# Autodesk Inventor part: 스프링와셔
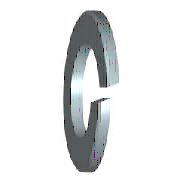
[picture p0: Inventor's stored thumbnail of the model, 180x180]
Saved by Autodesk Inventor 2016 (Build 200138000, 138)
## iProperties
Created: 2012-02
Part Number: 스프링와셔
Material: 강철, 연강
Description: 스프링 와셔
Document SubType Name: Modeling
Standard: JIS B 1251
Designer: mduedu
Standards Organization: JIS
Language: ko-KR
Size Designation: 번호 2 4
Categories: <MemberInstance><Categories><Category DisplayName="조임쇠" InternalName="e4da775c-781d-43d5-af7c-5136215cf5a6" Mnemonic="FSTN"><Category DisplayName="와셔" InternalN
Density: 7.85 g/cm^3
Appearance: 파란색 - 벽 페인트 - 광택
Mass: 0.246957 g
Surface Area: 1.02615 cm^2
Volume: 0.0314594 cm^3
IsCustomPart: 1
Author: mduedu
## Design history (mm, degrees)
sketch "스케치1"
  geometry: C1 r 3.8 at (0, 0); C2 r 2.05 at (0, 0); 1 further point
  constraints: 2 centre point, 2 coincident
  dimensions: "d0" = 4.1 diameter of C2 (= SD1); "d1" = 7.6 diameter of C1 (= SD2)
extrude "본체" new body sketch "스케치1" distance "d2" = 1 (= SD); taper "d3" = 0 deg
sketch "스케치2"
  geometry: L1 (0, -2.05)-(0, 2.05) reference; L2 (1, 3.8)-(1, -3.8) reference; L3 (-1.2, 0)-(7.2, 0) reference; L4 (0, -0.2)-(1, 0.164); L5 (0, 0.2)-(1, 0.564)
  constraints: 4 end point, 4 point on line, 1 parallel
  dimensions: "d4" = 0.2 distance from line of L3 L4.start (= 0.2 x SD); "d5" = 0.2 distance from line of L3 L5.start (= 0.2 x SD); "d6" = 70 deg angle of L2 L4 (= FAWI)
extrude "절단부" cut sketch "스케치2" stored distance "d7" = 1 (= SD); taper "d8" = 0 deg
workaxis "Work Axis1"
workplane "Work Plane1"
body "Solid1"
other parameters: "SD1" = 4.1 [user parameter; used in 1 equation term], "SD2" = 7.6 [user parameter; used in 1 equation term], "SD" = 1 [user parameter; used in 4 equation terms], "FAWI" = 70 deg [user parameter; used in 1 equation term], "d9" = 0, "d10" = 0, "d11" = 0, "d12" = 0, "SDI" = 1.4 [user parameter], "NND" = 4 [user parameter]
